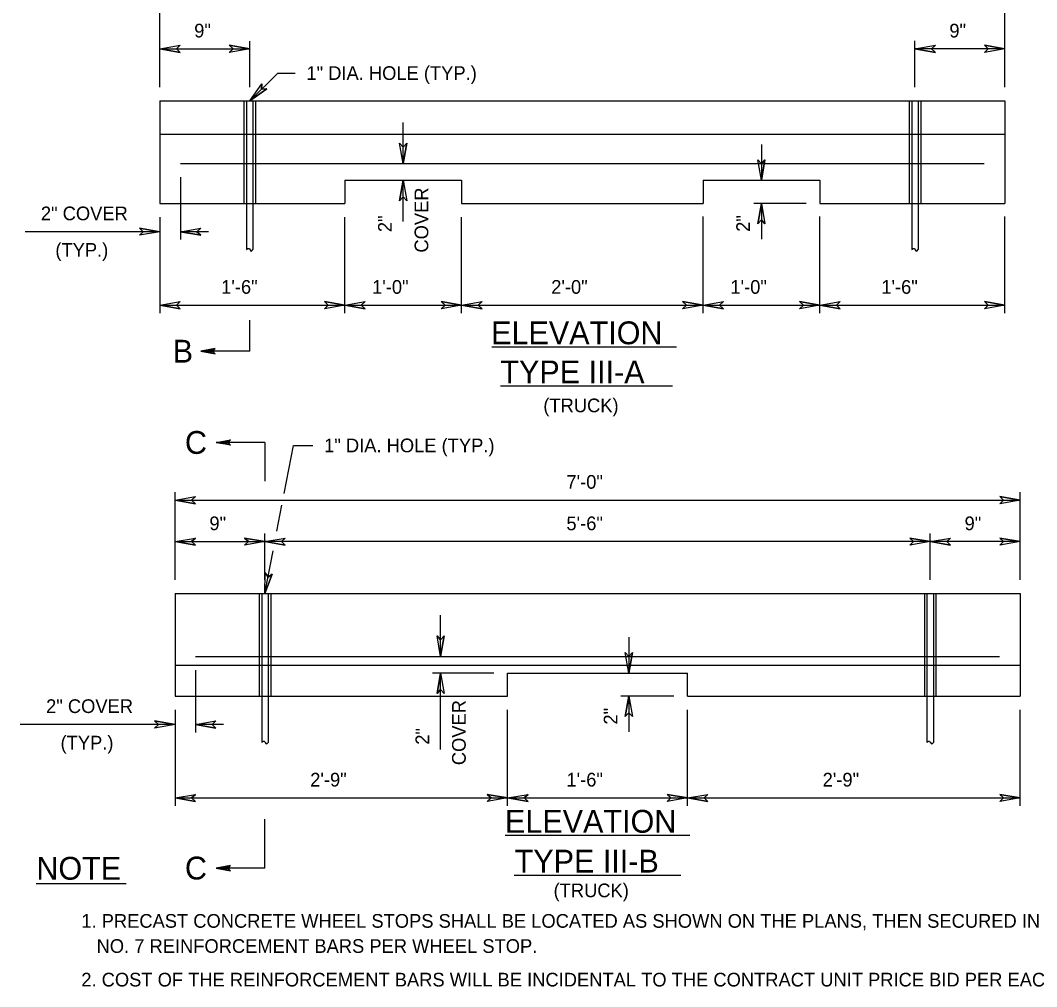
# Model space of a CAD drawing. Extents: x 12.4 to 19.6, y 6 to 16.2.
# Drawn here: x 12.354 to 16.806, y 7.49 to 11.724 of the extents above; entities that cross this region are included whole.
import ezdxf

# ---------------------------------------------------------------- set-up
doc = ezdxf.new("R2010")
doc.units = 0
for name, color, linetype in [('DETL-DIMS', 7, 'Continuous'), ('DETL-LINE', 7, 'Continuous'), ('DETL-NOTE', 7, 'Continuous'), ('DETL-TITL', 7, 'Continuous')]:
    doc.layers.add(name, color=color, linetype=linetype)

msp = doc.modelspace()

# ---------------------------------------------------------------- linework, layer by layer
at = {"layer": 'DETL-DIMS'}
for p, q in [((12.9654, 11.4321), (12.9654, 11.816)), ((16.6667, 11.4321), (16.6667, 11.816)), ((13.3592, 11.4321), (13.3592, 11.6324)), ((16.2729, 11.4321), (16.2729, 11.634)), ((12.9654, 11.5992), (13.0548, 11.615)), ((12.9654, 11.5992), (13.3592, 11.5992)), ((12.9654, 11.5992), (13.0548, 11.5835)), ((13.0379, 11.5992), (13.0548, 11.615)), ((13.0548, 11.5835), (13.0379, 11.5992)), ((13.3592, 11.5992), (13.2698, 11.615)), ((13.2698, 11.615), (13.2867, 11.5992)), ((13.3592, 11.5992), (13.2698, 11.5835)), ((13.2867, 11.5992), (13.2698, 11.5835)), ((16.2729, 11.5992), (16.3623, 11.615)), ((16.6667, 11.5992), (16.2729, 11.5992)), ((16.2729, 11.5992), (16.3623, 11.5835)), ((16.3454, 11.5992), (16.3623, 11.615)), ((16.3623, 11.5835), (16.3454, 11.5992)), ((16.6667, 11.5992), (16.5773, 11.615)), ((16.5773, 11.615), (16.5942, 11.5992)), ((16.6667, 11.5992), (16.5773, 11.5835)), ((16.5942, 11.5992), (16.5773, 11.5835)), ((13.3592, 11.3721), (13.4819, 11.4933)), ((13.4819, 11.4933), (13.5575, 11.4933)), ((13.3592, 11.3721), (13.4117, 11.4461)), ((13.4108, 11.4231), (13.4117, 11.4461)), ((13.3592, 11.3721), (13.4338, 11.4237)), ((13.4338, 11.4237), (13.4108, 11.4231)), ((14.0313, 11.0965), (14.0313, 11.2773)), ((14.0313, 11.0965), (14.0155, 11.1858)), ((14.0313, 11.169), (14.0155, 11.1858)), ((14.0313, 11.0965), (14.047, 11.1858)), ((14.047, 11.1858), (14.0313, 11.169)), ((15.6002, 11.1798), (15.6002, 11.0233)), ((15.6002, 11.0233), (15.5844, 11.1127)), ((15.6002, 11.0958), (15.5844, 11.1127)), ((15.6002, 11.0233), (15.6159, 11.1127)), ((15.6159, 11.1127), (15.6002, 11.0958)), ((13.0554, 11.0365), (13.0554, 10.7633)), ((14.0313, 11.0233), (14.0155, 10.934)), ((14.0313, 10.8425), (14.0313, 11.0233)), ((14.0313, 11.0233), (14.047, 10.934)), ((14.0155, 10.934), (14.0313, 10.9508)), ((14.0313, 10.9508), (14.047, 10.934)), ((15.7967, 10.9221), (15.5667, 10.9221)), ((15.6002, 10.9221), (15.5844, 10.8327)), ((15.6002, 10.9221), (15.6002, 10.7656)), ((15.6002, 10.9221), (15.6159, 10.8327)), ((12.9654, 10.8621), (12.9654, 10.4411)), ((13.7754, 10.4411), (13.7754, 10.8621)), ((14.2873, 10.4411), (14.2873, 10.8621)), ((15.3448, 10.4411), (15.3448, 10.8642)), ((15.8567, 10.4411), (15.8567, 10.8642)), ((16.6667, 10.4411), (16.6667, 10.8642)), ((15.5844, 10.8327), (15.6002, 10.8496)), ((15.6002, 10.8496), (15.6159, 10.8327)), ((12.9654, 10.7983), (12.3753, 10.7983)), ((12.9654, 10.7983), (12.876, 10.8141)), ((12.876, 10.8141), (12.8929, 10.7983)), ((12.9654, 10.7983), (12.876, 10.7826)), ((12.8929, 10.7983), (12.876, 10.7826)), ((13.0554, 10.7983), (13.1448, 10.8141)), ((13.1783, 10.7983), (13.0554, 10.7983)), ((13.0554, 10.7983), (13.1448, 10.7826)), ((13.1279, 10.7983), (13.1448, 10.8141)), ((13.1448, 10.7826), (13.1279, 10.7983)), ((12.9654, 10.4761), (13.0548, 10.4918)), ((12.9654, 10.4761), (13.7754, 10.4761)), ((12.9654, 10.4761), (13.0548, 10.4603)), ((13.0379, 10.4761), (13.0548, 10.4918)), ((13.0548, 10.4603), (13.0379, 10.4761)), ((13.7754, 10.4761), (13.686, 10.4918)), ((13.686, 10.4918), (13.7029, 10.4761)), ((13.7754, 10.4761), (13.686, 10.4603)), ((13.7029, 10.4761), (13.686, 10.4603)), ((13.7754, 10.4761), (13.8648, 10.4918)), ((13.7754, 10.4761), (14.2873, 10.4761)), ((13.7754, 10.4761), (13.8648, 10.4603)), ((13.8479, 10.4761), (13.8648, 10.4918)), ((13.8648, 10.4603), (13.8479, 10.4761)), ((14.2873, 10.4761), (14.1979, 10.4918)), ((14.1979, 10.4918), (14.2148, 10.4761)), ((14.2873, 10.4761), (14.1979, 10.4603)), ((14.2148, 10.4761), (14.1979, 10.4603)), ((14.2873, 10.4761), (14.3767, 10.4918)), ((14.2873, 10.4761), (15.3448, 10.4761)), ((14.2873, 10.4761), (14.3767, 10.4603)), ((14.3598, 10.4761), (14.3767, 10.4918)), ((14.3767, 10.4603), (14.3598, 10.4761)), ((15.3448, 10.4761), (15.2554, 10.4918)), ((15.2554, 10.4918), (15.2723, 10.4761)), ((15.3448, 10.4761), (15.2554, 10.4603)), ((15.2723, 10.4761), (15.2554, 10.4603)), ((15.3448, 10.4761), (15.4342, 10.4918)), ((15.3448, 10.4761), (15.8567, 10.4761)), ((15.3448, 10.4761), (15.4342, 10.4603)), ((15.4173, 10.4761), (15.4342, 10.4918)), ((15.4342, 10.4603), (15.4173, 10.4761)), ((15.8567, 10.4761), (15.7673, 10.4918)), ((15.7673, 10.4918), (15.7842, 10.4761)), ((15.8567, 10.4761), (15.7673, 10.4603)), ((15.7842, 10.4761), (15.7673, 10.4603)), ((15.8567, 10.4761), (15.946, 10.4918)), ((15.8567, 10.4761), (16.6667, 10.4761)), ((15.8567, 10.4761), (15.946, 10.4603)), ((15.9292, 10.4761), (15.946, 10.4918)), ((15.946, 10.4603), (15.9292, 10.4761)), ((16.6667, 10.4761), (16.5773, 10.4918)), ((16.5773, 10.4918), (16.5942, 10.4761)), ((16.6667, 10.4761), (16.5773, 10.4603)), ((16.5942, 10.4761), (16.5773, 10.4603)), ((13.3592, 10.2746), (13.3592, 10.4107)), ((13.3592, 10.2746), (13.1452, 10.2746)), ((13.4258, 9.8747), (13.2118, 9.8747)), ((13.4258, 9.8747), (13.4258, 9.7057)), ((13.5098, 9.6509), (13.5502, 9.8616)), ((13.5502, 9.8616), (13.6351, 9.8616)), ((13.032, 9.2731), (13.032, 9.6569)), ((13.032, 9.6219), (13.1214, 9.6377)), ((13.032, 9.6219), (16.7333, 9.6219)), ((13.032, 9.6219), (13.1214, 9.6062)), ((13.1045, 9.6219), (13.1214, 9.6377)), ((13.1214, 9.6062), (13.1045, 9.6219)), ((16.7333, 9.6219), (16.6439, 9.6377)), ((16.6439, 9.6377), (16.6608, 9.6219)), ((16.7333, 9.6219), (16.6439, 9.6062)), ((16.6608, 9.6219), (16.6439, 9.6062)), ((16.7333, 9.2731), (16.7333, 9.6569)), ((13.478, 9.4853), (13.5, 9.6003)), ((13.032, 9.4402), (13.1214, 9.4559)), ((13.032, 9.4402), (13.4258, 9.4402)), ((13.032, 9.4402), (13.1214, 9.4244)), ((13.1045, 9.4402), (13.1214, 9.4559)), ((13.1214, 9.4244), (13.1045, 9.4402)), ((13.4258, 9.4402), (13.3364, 9.4559)), ((13.3364, 9.4559), (13.3533, 9.4402)), ((13.4258, 9.4402), (13.3364, 9.4244)), ((13.3533, 9.4402), (13.3364, 9.4244)), ((13.4258, 9.2731), (13.4258, 9.4752)), ((13.4258, 9.4402), (13.5151, 9.4559)), ((16.3395, 9.4402), (13.4258, 9.4402)), ((13.4258, 9.4402), (13.5151, 9.4244)), ((13.4983, 9.4402), (13.5151, 9.4559)), ((13.5151, 9.4244), (13.4983, 9.4402)), ((16.3395, 9.4402), (16.2501, 9.4559)), ((16.2501, 9.4559), (16.267, 9.4402)), ((16.3395, 9.4402), (16.2501, 9.4244)), ((16.267, 9.4402), (16.2501, 9.4244)), ((16.3395, 9.2731), (16.3395, 9.4752)), ((16.3395, 9.4402), (16.4289, 9.4559)), ((16.7333, 9.4402), (16.3395, 9.4402)), ((16.3395, 9.4402), (16.4289, 9.4244)), ((16.412, 9.4402), (16.4289, 9.4559)), ((16.4289, 9.4244), (16.412, 9.4402)), ((16.7333, 9.4402), (16.6439, 9.4559)), ((16.6439, 9.4559), (16.6608, 9.4402)), ((16.7333, 9.4402), (16.6439, 9.4244)), ((16.6608, 9.4402), (16.6439, 9.4244)), ((13.4258, 9.2131), (13.4615, 9.3997)), ((13.4258, 9.2131), (13.4271, 9.3038)), ((13.4394, 9.2843), (13.4271, 9.3038)), ((13.4258, 9.2131), (13.458, 9.2979)), ((13.458, 9.2979), (13.4394, 9.2843)), ((14.1953, 8.9374), (14.1953, 9.1182)), ((14.1953, 8.9374), (14.1795, 9.0268)), ((14.1953, 9.0099), (14.1795, 9.0268)), ((14.1953, 8.9374), (14.211, 9.0268)), ((14.211, 9.0268), (14.1953, 9.0099)), ((15.0199, 9.0208), (15.0199, 8.8643)), ((15.0199, 8.8643), (15.0041, 8.9537)), ((15.0199, 8.9368), (15.0041, 8.9537)), ((15.0199, 8.8643), (15.0356, 8.9537)), ((15.0356, 8.9537), (15.0199, 8.9368)), ((13.122, 8.8774), (13.122, 8.6042)), ((14.4289, 8.8643), (14.1603, 8.8643)), ((14.1953, 8.8643), (14.1795, 8.7749)), ((14.1953, 8.5287), (14.1953, 8.8643)), ((14.1953, 8.8643), (14.211, 8.7749)), ((14.1795, 8.7749), (14.1953, 8.7918)), ((14.1953, 8.7918), (14.211, 8.7749)), ((15.2164, 8.7631), (14.9849, 8.7631)), ((15.0199, 8.7631), (15.0041, 8.6737)), ((15.0199, 8.7631), (15.0199, 8.6066)), ((15.0199, 8.7631), (15.0356, 8.6737)), ((13.032, 8.7031), (13.032, 8.2821)), ((14.4889, 8.2821), (14.4889, 8.7031)), ((15.0041, 8.6737), (15.0199, 8.6906)), ((15.0199, 8.6906), (15.0356, 8.6737)), ((15.2764, 8.2821), (15.2764, 8.7031)), ((16.7333, 8.2821), (16.7333, 8.7031)), ((13.032, 8.6392), (12.3544, 8.6392)), ((13.032, 8.6392), (12.9426, 8.6549)), ((12.9426, 8.6549), (12.9595, 8.6392)), ((13.032, 8.6392), (12.9426, 8.6234)), ((12.9595, 8.6392), (12.9426, 8.6234)), ((13.122, 8.6392), (13.2114, 8.6549)), ((13.2449, 8.6392), (13.122, 8.6392)), ((13.122, 8.6392), (13.2114, 8.6234)), ((13.1945, 8.6392), (13.2114, 8.6549)), ((13.2114, 8.6234), (13.1945, 8.6392)), ((13.032, 8.3171), (13.1214, 8.3328)), ((13.1045, 8.3171), (13.1214, 8.3328)), ((14.4889, 8.3171), (14.3995, 8.3328)), ((14.3995, 8.3328), (14.4164, 8.3171)), ((14.4889, 8.3171), (14.5783, 8.3328)), ((14.5614, 8.3171), (14.5783, 8.3328)), ((15.2764, 8.3171), (15.187, 8.3328)), ((15.187, 8.3328), (15.2039, 8.3171)), ((15.2764, 8.3171), (15.3658, 8.3328)), ((15.3489, 8.3171), (15.3658, 8.3328)), ((16.7333, 8.3171), (16.6439, 8.3328)), ((16.6439, 8.3328), (16.6608, 8.3171)), ((13.032, 8.3171), (14.4889, 8.3171)), ((13.032, 8.3171), (13.1214, 8.3013)), ((13.1214, 8.3013), (13.1045, 8.3171)), ((14.4889, 8.3171), (14.3995, 8.3013)), ((14.4164, 8.3171), (14.3995, 8.3013)), ((14.4889, 8.3171), (15.2764, 8.3171)), ((14.4889, 8.3171), (14.5783, 8.3013)), ((14.5783, 8.3013), (14.5614, 8.3171)), ((15.2764, 8.3171), (15.187, 8.3013)), ((15.2039, 8.3171), (15.187, 8.3013)), ((15.2764, 8.3171), (16.7333, 8.3171)), ((15.2764, 8.3171), (15.3658, 8.3013)), ((15.3658, 8.3013), (15.3489, 8.3171)), ((16.7333, 8.3171), (16.6439, 8.3013)), ((16.6608, 8.3171), (16.6439, 8.3013)), ((13.4258, 8.0098), (13.4258, 8.2238)), ((13.4258, 8.0098), (13.2118, 8.0098))]:
    msp.add_line(p, q, dxfattribs=at)
for points in [[(13.0548, 11.5835), (12.9654, 11.5992), (13.0548, 11.615), (13.0379, 11.5992)], [(13.2698, 11.615), (13.3592, 11.5992), (13.2698, 11.5835), (13.2867, 11.5992)], [(16.3623, 11.5835), (16.2729, 11.5992), (16.3623, 11.615), (16.3454, 11.5992)], [(16.5773, 11.615), (16.6667, 11.5992), (16.5773, 11.5835), (16.5942, 11.5992)], [(13.4338, 11.4237), (13.3592, 11.3721), (13.4117, 11.4461), (13.4108, 11.4231)], [(14.047, 11.1858), (14.0313, 11.0965), (14.0155, 11.1858), (14.0313, 11.169)], [(15.6159, 11.1127), (15.6002, 11.0233), (15.5844, 11.1127), (15.6002, 11.0958)], [(14.0155, 10.934), (14.0313, 11.0233), (14.047, 10.934), (14.0313, 10.9508)], [(15.5844, 10.8327), (15.6002, 10.9221), (15.6159, 10.8327), (15.6002, 10.8496)], [(12.876, 10.8141), (12.9654, 10.7983), (12.876, 10.7826), (12.8929, 10.7983)], [(13.1448, 10.7826), (13.0554, 10.7983), (13.1448, 10.8141), (13.1279, 10.7983)], [(13.0548, 10.4603), (12.9654, 10.4761), (13.0548, 10.4918), (13.0379, 10.4761)], [(13.686, 10.4918), (13.7754, 10.4761), (13.686, 10.4603), (13.7029, 10.4761)], [(13.8648, 10.4603), (13.7754, 10.4761), (13.8648, 10.4918), (13.8479, 10.4761)], [(14.1979, 10.4918), (14.2873, 10.4761), (14.1979, 10.4603), (14.2148, 10.4761)], [(14.3767, 10.4603), (14.2873, 10.4761), (14.3767, 10.4918), (14.3598, 10.4761)], [(15.2554, 10.4918), (15.3448, 10.4761), (15.2554, 10.4603), (15.2723, 10.4761)], [(15.4342, 10.4603), (15.3448, 10.4761), (15.4342, 10.4918), (15.4173, 10.4761)], [(15.7673, 10.4918), (15.8567, 10.4761), (15.7673, 10.4603), (15.7842, 10.4761)], [(15.946, 10.4603), (15.8567, 10.4761), (15.946, 10.4918), (15.9292, 10.4761)], [(16.5773, 10.4918), (16.6667, 10.4761), (16.5773, 10.4603), (16.5942, 10.4761)], [(13.1214, 9.6062), (13.032, 9.6219), (13.1214, 9.6377), (13.1045, 9.6219)], [(16.6439, 9.6377), (16.7333, 9.6219), (16.6439, 9.6062), (16.6608, 9.6219)], [(13.1214, 9.4244), (13.032, 9.4402), (13.1214, 9.4559), (13.1045, 9.4402)], [(13.3364, 9.4559), (13.4258, 9.4402), (13.3364, 9.4244), (13.3533, 9.4402)], [(13.5151, 9.4244), (13.4258, 9.4402), (13.5151, 9.4559), (13.4983, 9.4402)], [(16.2501, 9.4559), (16.3395, 9.4402), (16.2501, 9.4244), (16.267, 9.4402)], [(16.4289, 9.4244), (16.3395, 9.4402), (16.4289, 9.4559), (16.412, 9.4402)], [(16.6439, 9.4559), (16.7333, 9.4402), (16.6439, 9.4244), (16.6608, 9.4402)], [(13.458, 9.2979), (13.4258, 9.2131), (13.4271, 9.3038), (13.4394, 9.2843)], [(14.211, 9.0268), (14.1953, 8.9374), (14.1795, 9.0268), (14.1953, 9.0099)], [(15.0356, 8.9537), (15.0199, 8.8643), (15.0041, 8.9537), (15.0199, 8.9368)], [(14.1795, 8.7749), (14.1953, 8.8643), (14.211, 8.7749), (14.1953, 8.7918)], [(15.0041, 8.6737), (15.0199, 8.7631), (15.0356, 8.6737), (15.0199, 8.6906)], [(12.9426, 8.6549), (13.032, 8.6392), (12.9426, 8.6234), (12.9595, 8.6392)], [(13.2114, 8.6234), (13.122, 8.6392), (13.2114, 8.6549), (13.1945, 8.6392)], [(13.1214, 8.3013), (13.032, 8.3171), (13.1214, 8.3328), (13.1045, 8.3171)], [(14.3995, 8.3328), (14.4889, 8.3171), (14.3995, 8.3013), (14.4164, 8.3171)], [(14.5783, 8.3013), (14.4889, 8.3171), (14.5783, 8.3328), (14.5614, 8.3171)], [(15.187, 8.3328), (15.2764, 8.3171), (15.187, 8.3013), (15.2039, 8.3171)], [(15.3658, 8.3013), (15.2764, 8.3171), (15.3658, 8.3328), (15.3489, 8.3171)], [(16.6439, 8.3328), (16.7333, 8.3171), (16.6439, 8.3013), (16.6608, 8.3171)]]:
    msp.add_lwpolyline(points, close=True, dxfattribs=at)
for points in [[(13.1452, 10.2746), (13.208, 10.2627), (13.2033, 10.2661), (13.2008, 10.2703), (13.2, 10.2746), (13.2008, 10.2787), (13.2033, 10.2829), (13.208, 10.2863), (13.1452, 10.2746), (13.2033, 10.2829), (13.2008, 10.2787), (13.1452, 10.2746), (13.2, 10.2746), (13.2008, 10.2703), (13.1452, 10.2746), (13.2033, 10.2661)], [(13.2118, 9.8747), (13.2746, 9.8864), (13.2699, 9.883), (13.2674, 9.8788), (13.2666, 9.8747), (13.2674, 9.8704), (13.2699, 9.8662), (13.2746, 9.8628), (13.2118, 9.8747), (13.2699, 9.8662), (13.2674, 9.8704), (13.2118, 9.8747), (13.2666, 9.8747), (13.2674, 9.8788), (13.2118, 9.8747), (13.2699, 9.883)], [(13.2118, 8.0098), (13.2746, 7.9982), (13.2699, 8.0014), (13.2674, 8.0057), (13.2666, 8.0098), (13.2674, 8.0141), (13.2699, 8.0183), (13.2746, 8.0217), (13.2118, 8.0098), (13.2699, 8.0183), (13.2674, 8.0141), (13.2118, 8.0098), (13.2666, 8.0098), (13.2674, 8.0057), (13.2118, 8.0098), (13.2699, 8.0014)]]:
    msp.add_lwpolyline(points, dxfattribs=at)
at = {"layer": 'DETL-LINE'}
for p, q in [((12.9654, 11.3721), (16.6667, 11.3721)), ((12.9654, 11.3721), (12.9654, 10.9221)), ((13.3338, 11.3721), (13.3338, 10.9221)), ((13.3338, 11.3721), (13.3844, 11.3721)), ((13.345, 11.3721), (13.345, 10.9221)), ((13.3732, 11.3721), (13.3732, 10.9221)), ((13.3844, 11.3721), (13.3844, 10.9221)), ((16.2475, 11.3721), (16.2475, 10.9221)), ((16.2475, 11.3721), (16.2982, 11.3721)), ((16.2588, 11.3721), (16.2588, 10.9221)), ((16.2869, 11.3721), (16.2869, 10.9221)), ((16.2982, 11.3721), (16.2982, 10.9221)), ((16.6667, 11.3721), (16.6667, 10.9221)), ((12.9654, 11.2258), (16.6667, 11.2258)), ((13.0554, 11.0965), (15.5775, 11.0965)), ((15.5775, 11.0965), (16.5767, 11.0965)), ((13.7754, 11.0233), (13.7754, 10.9221)), ((13.7754, 11.0233), (14.2873, 11.0233)), ((14.2873, 11.0233), (14.2873, 10.9221)), ((15.3448, 11.0233), (15.3448, 10.9221)), ((15.3448, 11.0233), (15.8567, 11.0233)), ((15.8567, 11.0233), (15.8567, 10.9221)), ((12.9654, 10.9221), (13.7754, 10.9221)), ((13.345, 10.9221), (13.345, 10.7196)), ((13.3732, 10.9221), (13.3732, 10.7196)), ((14.2873, 10.9221), (15.3448, 10.9221)), ((15.8567, 10.9221), (16.6667, 10.9221)), ((16.2588, 10.9221), (16.2588, 10.7196)), ((16.2869, 10.9221), (16.2869, 10.7196)), ((13.032, 9.2131), (16.7333, 9.2131)), ((13.032, 9.2131), (13.032, 8.7631)), ((13.4004, 9.2131), (13.4004, 8.7631)), ((13.4004, 9.2131), (13.451, 9.2131)), ((13.4116, 9.2131), (13.4116, 8.7631)), ((13.4398, 9.2131), (13.4398, 8.7631)), ((13.451, 9.2131), (13.451, 8.7631)), ((16.3141, 9.2131), (16.3141, 8.7631)), ((16.3141, 9.2131), (16.3648, 9.2131)), ((16.3254, 9.2131), (16.3254, 8.7631)), ((16.3535, 9.2131), (16.3535, 8.7631)), ((16.3648, 9.2131), (16.3648, 8.7631)), ((16.7333, 9.2131), (16.7333, 8.7631)), ((13.122, 8.9374), (14.9771, 8.9374)), ((14.9771, 8.9374), (16.6433, 8.9374)), ((13.032, 8.8988), (14.9861, 8.8988)), ((14.4889, 8.7631), (14.4889, 8.8643)), ((14.4889, 8.8643), (15.2764, 8.8643)), ((14.9861, 8.8988), (16.7333, 8.8988)), ((15.2764, 8.7631), (15.2764, 8.8643)), ((13.032, 8.7631), (14.4889, 8.7631)), ((13.4116, 8.7631), (13.4116, 8.5606)), ((13.4398, 8.7631), (13.4398, 8.5606)), ((15.2764, 8.7631), (16.7333, 8.7631)), ((16.3254, 8.7631), (16.3254, 8.5606)), ((16.3535, 8.7631), (16.3535, 8.5606))]:
    msp.add_line(p, q, dxfattribs=at)
for points in [[(13.345, 10.7196), (13.3555, 10.725), (13.3653, 10.713), (13.3732, 10.7196)], [(16.2588, 10.7196), (16.2693, 10.725), (16.279, 10.713), (16.2869, 10.7196)], [(13.4116, 8.5606), (13.4221, 8.5658), (13.4319, 8.5539), (13.4398, 8.5606)], [(16.3254, 8.5606), (16.3359, 8.5658), (16.3456, 8.5539), (16.3535, 8.5606)]]:
    msp.add_spline(points, degree=3, dxfattribs=at)
at = {"layer": 'DETL-NOTE'}
msp.add_line((12.4245, 7.9417), (12.8185, 7.9417), dxfattribs=at)
at = {"layer": 'DETL-TITL'}
for p, q in [((14.4194, 10.294), (15.2278, 10.294)), ((14.458, 10.1226), (15.211, 10.1226)), ((14.4782, 8.1535), (15.2872, 8.1535)), ((14.518, 7.979), (15.2474, 7.979))]:
    msp.add_line(p, q, dxfattribs=at)

# ---------------------------------------------------------------- texts
at = {"layer": 'DETL-NOTE'}
for s, height, p in [('9"', 0.06, (13.116, 11.6492)), ('9"', 0.06, (16.4235, 11.6492)), ('1" DIA. HOLE (TYP.)', 0.06, (13.6075, 11.4633)), ('2" COVER', 0.06, (12.4445, 10.8483)), ('(TYP.)', 0.06, (12.5078, 10.6883)), ('1\'-6"', 0.06, (13.2341, 10.5261)), ('1\'-0"', 0.06, (13.8951, 10.5261)), ('2\'-0"', 0.06, (14.6797, 10.5261)), ('1\'-0"', 0.06, (15.4645, 10.5261)), ('1\'-6"', 0.06, (16.1254, 10.5261)), ('B', 0.1, (13.0217, 10.2246)), ('(TRUCK)', 0.06, (14.6451, 10.0071)), ('C', 0.1, (13.0753, 9.8247)), ('1" DIA. HOLE (TYP.)', 0.06, (13.6851, 9.8316)), ('7\'-0"', 0.06, (14.7463, 9.6719)), ('9"', 0.06, (13.1826, 9.4902)), ('5\'-6"', 0.06, (14.7463, 9.4902)), ('9"', 0.06, (16.4901, 9.4902)), ('2" COVER', 0.06, (12.4673, 8.6892)), ('(TYP.)', 0.06, (12.5306, 8.5292)), ('2\'-9"', 0.06, (13.6241, 8.3671)), ('1\'-6"', 0.06, (14.7463, 8.3671)), ('2\'-9"', 0.06, (15.8685, 8.3671)), ('NOTE', 0.1, (12.4245, 7.9588)), ('C', 0.1, (13.0753, 7.9598)), ('(TRUCK)', 0.06, (14.69, 7.8819)), ('1. PRECAST CONCRETE WHEEL STOPS SHALL BE LOCATED AS SHOWN ON THE PLANS, THEN SECURED IN PLACE WITH TWO (2)', 0.06, (12.6215, 7.7482)), ('   NO. 7 REINFORCEMENT BARS PER WHEEL STOP.', 0.06, (12.6215, 7.6382)), ('2. COST OF THE REINFORCEMENT BARS WILL BE INCIDENTAL TO THE CONTRACT UNIT PRICE BID PER EACH FOR THE WHEEL STOPS.', 0.06, (12.6215, 7.4909))]:
    msp.add_text(s, height=height, dxfattribs=at).set_placement(p)
for s, p in [('COVER', (14.1413, 10.7066)), ('2"', (13.9813, 10.7962)), ('2"', (15.5502, 10.7975)), ('COVER', (14.3053, 8.4606)), ('2"', (14.9699, 8.6385)), ('2"', (14.1453, 8.5502))]:
    msp.add_text(s, height=0.06, rotation=90, dxfattribs=at).set_placement(p)
at = {"layer": 'DETL-TITL'}
for s, p in [('ELEVATION', (14.4165, 10.3051)), ('TYPE III-A', (14.4569, 10.1337)), ('ELEVATION', (14.4772, 8.1646)), ('TYPE III-B', (14.5194, 7.9901))]:
    msp.add_text(s, height=0.1, dxfattribs=at).set_placement(p)

doc.saveas('drawing.dxf')
